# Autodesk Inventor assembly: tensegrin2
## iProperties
Author: MAX
Created: 2002-09
Part Number: tensegrin2
Document SubType Name: Baugruppe
Designer: MAX
Control State: 0
Master: False
Checked Out: False
PropertySet Name: Design Tracking Control
Shininess: 20.0
Angle Display Precision: 2
Document Length Units: 11269
Document Angle Units: 11283
Document Time Units: 11279
Document Mass Units: 11290
Document Length Units Precision: 3
Document Angle Units Precision: 2
Compacted: False
PropertySet Name: _Private Model Information
Density: 0.0
Volumn: 0.0
Area: 0.0
PropertySet Name: Model Information
